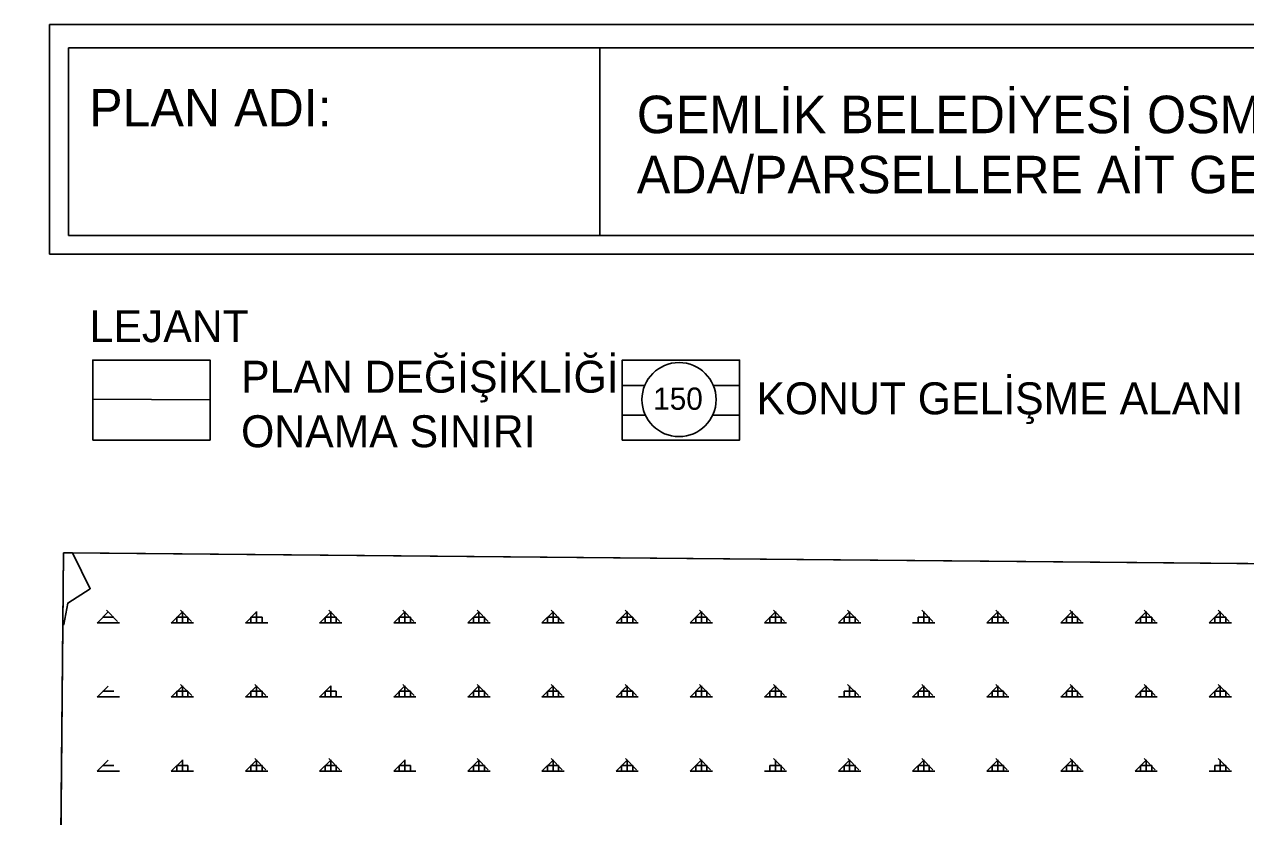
# Model space of a CAD drawing. Extents: x 427903 to 430077, y 4477233 to 4480385.
# Drawn here: x 427903 to 428726, y 4479851 to 4480385 of the extents above; entities that cross this region are included whole.
import ezdxf

# ---------------------------------------------------------------- set-up
doc = ezdxf.new("R2010")
doc.units = 0
for name, color, linetype in [('ADA', 7, 'Continuous'), ('Level 53', 7, 'Continuous'), ('PL_AYA_ORMAN', 7, 'Continuous'), ('PL_KA_TARIM_DIGER', 7, 'Continuous'), ('PL_KON_ONE_150', 7, 'Continuous'), ('rezerv yapı alan', 7, 'Continuous'), ('SM_DAIRE', 7, 'Continuous'), ('SM_TAKS', 7, 'Continuous'), ('SN_BMK Değişiklik', 7, 'Continuous'), ('SıNıR', 7, 'Continuous'), ('TR_ORMAN', 7, 'Continuous'), ('TR_ORTAGELISME', 7, 'Continuous')]:
    doc.layers.add(name, color=color, linetype=linetype)

msp = doc.modelspace()

# ---------------------------------------------------------------- linework, layer by layer
at = {"layer": 'ADA'}
for p, q in [((427935.26, 4480028.56), (427934.93, 4480028.9)), ((427946.96, 4480004.75), (427935.26, 4480028.56)), ((427931.77, 4479995.04), (427946.96, 4480004.75)), ((427929.05, 4479980.53), (427931.77, 4479995.04)), ((427928.55, 4479980.19), (427929.05, 4479980.53))]:
    msp.add_line(p, q, dxfattribs=at)
at = {"layer": 'Level 53'}
for p, q in [((427919.44, 4480385.36), (429266.95, 4480385.36)), ((427919.44, 4480230.37), (427919.44, 4480385.36)), ((427932.36, 4480369.55), (429254.03, 4480369.55)), ((427932.36, 4480243.03), (427932.36, 4480369.55)), ((428290.69, 4480369.55), (428290.69, 4480243.03)), ((427932.36, 4480243.03), (428290.69, 4480243.03)), ((428290.69, 4480243.03), (429254.03, 4480243.03)), ((427919.44, 4480230.37), (429266.95, 4480230.37))]:
    msp.add_line(p, q, dxfattribs=at)
for points in [[(427948.62, 4480105.05), (428027.85, 4480105.05), (428027.85, 4480158.93), (427948.62, 4480158.93), (427948.62, 4480105.05)], [(428305.75, 4480105.05), (428384.98, 4480105.05), (428384.98, 4480158.93), (428305.75, 4480158.93), (428305.75, 4480105.05)]]:
    msp.add_lwpolyline(points, dxfattribs=at)
at = {"layer": 'PL_AYA_ORMAN'}
for points in [[(427934.93, 4480028.9), (427935.26, 4480028.56), (427946.96, 4480004.75), (427931.77, 4479995.04), (427929.05, 4479980.53), (427928.55, 4479980.19)], [(429043.16, 4480018.9), (427934.93, 4480028.9)], [(427928.55, 4479980.19), (427923.1, 4479407.43)]]:
    msp.add_lwpolyline(points, dxfattribs=at)
at = {"layer": 'PL_KA_TARIM_DIGER'}
for points in [[(427928.55, 4479980.19), (427929.02, 4480028.95), (427934.93, 4480028.9)], [(427934.93, 4480028.9), (427935.26, 4480028.56), (427946.96, 4480004.75), (427931.77, 4479995.04), (427929.05, 4479980.53), (427928.55, 4479980.19)]]:
    msp.add_lwpolyline(points, dxfattribs=at)
at = {"layer": 'PL_KON_ONE_150'}
msp.add_lwpolyline([(428305.75, 4480158.93), (428305.75, 4480105.05), (428384.98, 4480105.05), (428384.98, 4480158.93), (428305.75, 4480158.93)], dxfattribs=at)
at = {"layer": 'rezerv yapı alan'}
msp.add_lwpolyline([(430040.04, 4478910.67), (430050.52, 4480009.82), (427929.02, 4480028.95), (427921.98, 4479290.57)], dxfattribs=at)
at = {"layer": 'SM_DAIRE'}
msp.add_circle((428344.11, 4480132.32), 25, dxfattribs=at)
at = {"layer": 'SN_BMK Değişiklik'}
msp.add_line((427948.62, 4480132.69), (428027.85, 4480132.13), dxfattribs=at)
at = {"layer": 'SıNıR'}
for p, q in [((427902.58, 4477253.75), (427929.02, 4480028.95)), ((427929.02, 4480028.95), (430050.52, 4480009.82))]:
    msp.add_line(p, q, dxfattribs=at)
at = {"layer": 'TR_ORMAN'}
for p, q in [((427951.63, 4479981.62), (427959.13, 4479989.12)), ((427965.36, 4479982.71), (427957.87, 4479990.21)), ((428001.63, 4479981.63), (428009.13, 4479989.13)), ((428015.36, 4479982.71), (428007.86, 4479990.21)), ((428009.14, 4479981.81), (428009.14, 4479989.31)), ((428051.63, 4479981.64), (428059.13, 4479989.13)), ((428059.14, 4479981.81), (428059.14, 4479989.31)), ((428101.63, 4479981.64), (428109.13, 4479989.14)), ((428115.34, 4479982.71), (428107.84, 4479990.21)), ((428109.14, 4479981.81), (428109.14, 4479989.31)), ((428109.14, 4479981.81), (428109.14, 4479989.31)), ((428151.63, 4479981.65), (428159.13, 4479989.15)), ((428165.33, 4479982.71), (428157.84, 4479990.21)), ((428159.14, 4479981.81), (428159.14, 4479989.31)), ((428159.14, 4479981.81), (428159.14, 4479989.31)), ((428201.63, 4479981.66), (428209.13, 4479989.16)), ((428215.33, 4479982.71), (428207.83, 4479990.21)), ((428209.14, 4479981.81), (428209.14, 4479989.31)), ((428251.63, 4479981.66), (428259.13, 4479989.16)), ((428265.32, 4479982.71), (428257.82, 4479990.21)), ((428259.14, 4479981.81), (428259.14, 4479989.31)), ((428301.63, 4479981.67), (428309.13, 4479989.17)), ((428315.31, 4479982.71), (428307.81, 4479990.21)), ((428309.14, 4479981.81), (428309.14, 4479989.31)), ((428351.63, 4479981.68), (428359.13, 4479989.18)), ((428365.3, 4479982.71), (428357.81, 4479990.21)), ((428359.14, 4479981.81), (428359.14, 4479989.31)), ((428401.63, 4479981.68), (428409.13, 4479989.18)), ((428415.3, 4479982.71), (428407.8, 4479990.21)), ((428409.14, 4479981.81), (428409.14, 4479989.31)), ((428409.14, 4479981.81), (428409.14, 4479989.31)), ((428451.63, 4479981.69), (428459.13, 4479989.19)), ((428465.29, 4479982.71), (428457.79, 4479990.21)), ((428459.14, 4479981.81), (428459.14, 4479989.31)), ((428515.28, 4479982.71), (428507.78, 4479990.21)), ((428509.14, 4479981.81), (428509.14, 4479989.31)), ((428551.63, 4479981.71), (428559.13, 4479989.2)), ((428565.27, 4479982.71), (428557.78, 4479990.21)), ((428559.14, 4479981.81), (428559.14, 4479989.31)), ((428601.63, 4479981.71), (428609.13, 4479989.21)), ((428615.27, 4479982.71), (428607.77, 4479990.21)), ((428609.14, 4479981.81), (428609.14, 4479989.31)), ((428651.63, 4479981.72), (428659.13, 4479989.22)), ((428665.26, 4479982.71), (428657.76, 4479990.21)), ((428659.14, 4479981.81), (428659.14, 4479989.31)), ((428701.63, 4479981.73), (428709.13, 4479989.23)), ((428715.25, 4479982.71), (428707.75, 4479990.21)), ((428709.14, 4479981.81), (428709.14, 4479989.31)), ((427951.64, 4479981.81), (427966.64, 4479981.81)), ((427955.39, 4479985.56), (427962.89, 4479985.56)), ((428001.64, 4479981.81), (428016.64, 4479981.81)), ((428005.39, 4479981.81), (428005.39, 4479985.56)), ((428005.39, 4479985.56), (428012.89, 4479985.56)), ((428012.89, 4479981.81), (428012.89, 4479985.56)), ((428051.64, 4479981.81), (428066.64, 4479981.81)), ((428055.39, 4479985.56), (428062.89, 4479985.56)), ((428055.39, 4479981.81), (428055.39, 4479985.56)), ((428062.89, 4479981.81), (428062.89, 4479985.56)), ((428101.64, 4479981.81), (428116.64, 4479981.81)), ((428105.39, 4479981.81), (428105.39, 4479985.56)), ((428105.39, 4479981.81), (428105.39, 4479985.56)), ((428105.39, 4479985.56), (428112.89, 4479985.56)), ((428112.89, 4479981.81), (428112.89, 4479985.56)), ((428151.64, 4479981.81), (428166.64, 4479981.81)), ((428155.39, 4479981.81), (428155.39, 4479985.56)), ((428155.39, 4479981.81), (428155.39, 4479985.56)), ((428155.39, 4479985.56), (428162.89, 4479985.56)), ((428162.89, 4479981.81), (428162.89, 4479985.56)), ((428162.89, 4479981.81), (428162.89, 4479985.56)), ((428201.64, 4479981.81), (428216.64, 4479981.81)), ((428205.39, 4479981.81), (428205.39, 4479985.56)), ((428205.39, 4479985.56), (428212.89, 4479985.56)), ((428212.89, 4479981.81), (428212.89, 4479985.56)), ((428251.64, 4479981.81), (428266.64, 4479981.81)), ((428255.39, 4479981.81), (428255.39, 4479985.56)), ((428255.39, 4479985.56), (428262.89, 4479985.56)), ((428262.89, 4479981.81), (428262.89, 4479985.56)), ((428301.64, 4479981.81), (428316.64, 4479981.81)), ((428305.39, 4479981.81), (428305.39, 4479985.56)), ((428305.39, 4479985.56), (428312.89, 4479985.56)), ((428312.89, 4479981.81), (428312.89, 4479985.56)), ((428351.64, 4479981.81), (428366.64, 4479981.81)), ((428355.39, 4479981.81), (428355.39, 4479985.56)), ((428355.39, 4479985.56), (428362.89, 4479985.56)), ((428362.89, 4479981.81), (428362.89, 4479985.56)), ((428362.89, 4479981.81), (428362.89, 4479985.56)), ((428401.64, 4479981.81), (428416.64, 4479981.81)), ((428405.39, 4479981.81), (428405.39, 4479985.56)), ((428405.39, 4479985.56), (428412.89, 4479985.56)), ((428412.89, 4479981.81), (428412.89, 4479985.56)), ((428412.89, 4479981.81), (428412.89, 4479985.56)), ((428451.64, 4479981.81), (428466.64, 4479981.81)), ((428455.39, 4479981.81), (428455.39, 4479985.56)), ((428455.39, 4479985.56), (428462.89, 4479985.56)), ((428462.89, 4479981.81), (428462.89, 4479985.56)), ((428501.64, 4479981.81), (428516.64, 4479981.81)), ((428505.39, 4479981.81), (428505.39, 4479985.56)), ((428505.39, 4479985.56), (428512.89, 4479985.56)), ((428512.89, 4479981.81), (428512.89, 4479985.56)), ((428551.64, 4479981.81), (428566.64, 4479981.81)), ((428555.39, 4479981.81), (428555.39, 4479985.56)), ((428555.39, 4479985.56), (428562.89, 4479985.56)), ((428562.89, 4479981.81), (428562.89, 4479985.56)), ((428601.64, 4479981.81), (428616.64, 4479981.81)), ((428605.39, 4479981.81), (428605.39, 4479985.56)), ((428605.39, 4479985.56), (428612.89, 4479985.56)), ((428612.89, 4479981.81), (428612.89, 4479985.56)), ((428651.64, 4479981.81), (428666.64, 4479981.81)), ((428655.39, 4479981.81), (428655.39, 4479985.56)), ((428655.39, 4479985.56), (428662.89, 4479985.56)), ((428662.89, 4479981.81), (428662.89, 4479985.56)), ((428701.64, 4479981.81), (428716.64, 4479981.81)), ((428705.39, 4479981.81), (428705.39, 4479985.56)), ((428705.39, 4479981.81), (428705.39, 4479985.56)), ((428705.39, 4479985.56), (428712.89, 4479985.56)), ((428712.89, 4479981.81), (428712.89, 4479985.56)), ((427951.63, 4479931.63), (427959.13, 4479939.13)), ((428001.63, 4479931.64), (428009.13, 4479939.13)), ((428015.39, 4479932.68), (428007.89, 4479940.18)), ((428009.14, 4479931.81), (428009.14, 4479939.31)), ((428051.63, 4479931.64), (428059.13, 4479939.14)), ((428065.38, 4479932.68), (428057.88, 4479940.18)), ((428059.14, 4479931.81), (428059.14, 4479939.31)), ((428101.63, 4479931.65), (428109.13, 4479939.15)), ((428109.14, 4479931.81), (428109.14, 4479939.31)), ((428109.14, 4479931.81), (428109.14, 4479939.31)), ((428151.63, 4479931.66), (428159.13, 4479939.16)), ((428165.37, 4479932.68), (428157.87, 4479940.18)), ((428159.14, 4479931.81), (428159.14, 4479939.31)), ((428159.14, 4479931.81), (428159.14, 4479939.31)), ((428201.63, 4479931.66), (428209.13, 4479939.16)), ((428215.36, 4479932.68), (428207.86, 4479940.18)), ((428209.14, 4479931.81), (428209.14, 4479939.31)), ((428251.63, 4479931.67), (428259.13, 4479939.17)), ((428265.35, 4479932.68), (428257.85, 4479940.18)), ((428259.14, 4479931.81), (428259.14, 4479939.31)), ((428301.63, 4479931.68), (428309.13, 4479939.18)), ((428315.34, 4479932.68), (428307.84, 4479940.18)), ((428309.14, 4479931.81), (428309.14, 4479939.31)), ((428351.63, 4479931.69), (428359.13, 4479939.18)), ((428365.34, 4479932.68), (428357.84, 4479940.18)), ((428359.14, 4479931.81), (428359.14, 4479939.31)), ((428401.63, 4479931.69), (428409.13, 4479939.19)), ((428415.33, 4479932.68), (428407.83, 4479940.18)), ((428409.14, 4479931.81), (428409.14, 4479939.31)), ((428409.14, 4479931.81), (428409.14, 4479939.31)), ((428465.32, 4479932.68), (428457.82, 4479940.18)), ((428459.14, 4479931.81), (428459.14, 4479939.31)), ((428501.63, 4479931.71), (428509.13, 4479939.21)), ((428515.31, 4479932.68), (428507.81, 4479940.18)), ((428509.14, 4479931.81), (428509.14, 4479939.31)), ((428551.63, 4479931.71), (428559.13, 4479939.21)), ((428565.31, 4479932.68), (428557.81, 4479940.18)), ((428559.14, 4479931.81), (428559.14, 4479939.31)), ((428601.63, 4479931.72), (428609.13, 4479939.22)), ((428615.3, 4479932.68), (428607.8, 4479940.18)), ((428609.14, 4479931.81), (428609.14, 4479939.31)), ((428651.63, 4479931.73), (428659.13, 4479939.23)), ((428665.29, 4479932.68), (428657.79, 4479940.18)), ((428659.14, 4479931.81), (428659.14, 4479939.31)), ((428701.63, 4479931.73), (428709.13, 4479939.23)), ((428715.28, 4479932.68), (428707.78, 4479940.18)), ((428709.14, 4479931.81), (428709.14, 4479939.31)), ((427951.64, 4479931.81), (427966.64, 4479931.81)), ((427955.39, 4479935.56), (427962.89, 4479935.56)), ((428001.64, 4479931.81), (428016.64, 4479931.81)), ((428005.39, 4479931.81), (428005.39, 4479935.56)), ((428005.39, 4479935.56), (428012.89, 4479935.56)), ((428012.89, 4479931.81), (428012.89, 4479935.56)), ((428051.64, 4479931.81), (428066.64, 4479931.81)), ((428055.39, 4479935.56), (428062.89, 4479935.56)), ((428055.39, 4479931.81), (428055.39, 4479935.56)), ((428062.89, 4479931.81), (428062.89, 4479935.56)), ((428101.64, 4479931.81), (428116.64, 4479931.81)), ((428105.39, 4479931.81), (428105.39, 4479935.56)), ((428105.39, 4479931.81), (428105.39, 4479935.56)), ((428105.39, 4479935.56), (428112.89, 4479935.56)), ((428112.89, 4479931.81), (428112.89, 4479935.56)), ((428151.64, 4479931.81), (428166.64, 4479931.81)), ((428155.39, 4479931.81), (428155.39, 4479935.56)), ((428155.39, 4479931.81), (428155.39, 4479935.56)), ((428155.39, 4479935.56), (428162.89, 4479935.56)), ((428162.89, 4479931.81), (428162.89, 4479935.56)), ((428162.89, 4479931.81), (428162.89, 4479935.56)), ((428201.64, 4479931.81), (428216.64, 4479931.81)), ((428205.39, 4479931.81), (428205.39, 4479935.56)), ((428205.39, 4479935.56), (428212.89, 4479935.56)), ((428212.89, 4479931.81), (428212.89, 4479935.56)), ((428251.64, 4479931.81), (428266.64, 4479931.81)), ((428255.39, 4479931.81), (428255.39, 4479935.56)), ((428255.39, 4479935.56), (428262.89, 4479935.56)), ((428262.89, 4479931.81), (428262.89, 4479935.56)), ((428301.64, 4479931.81), (428316.64, 4479931.81)), ((428305.39, 4479931.81), (428305.39, 4479935.56)), ((428305.39, 4479935.56), (428312.89, 4479935.56)), ((428312.89, 4479931.81), (428312.89, 4479935.56)), ((428351.64, 4479931.81), (428366.64, 4479931.81)), ((428355.39, 4479931.81), (428355.39, 4479935.56)), ((428355.39, 4479935.56), (428362.89, 4479935.56)), ((428362.89, 4479931.81), (428362.89, 4479935.56)), ((428362.89, 4479931.81), (428362.89, 4479935.56)), ((428401.64, 4479931.81), (428416.64, 4479931.81)), ((428405.39, 4479931.81), (428405.39, 4479935.56)), ((428405.39, 4479935.56), (428412.89, 4479935.56)), ((428412.89, 4479931.81), (428412.89, 4479935.56)), ((428412.89, 4479931.81), (428412.89, 4479935.56)), ((428451.64, 4479931.81), (428466.64, 4479931.81)), ((428455.39, 4479931.81), (428455.39, 4479935.56)), ((428455.39, 4479935.56), (428462.89, 4479935.56)), ((428462.89, 4479931.81), (428462.89, 4479935.56)), ((428501.64, 4479931.81), (428516.64, 4479931.81)), ((428505.39, 4479931.81), (428505.39, 4479935.56)), ((428505.39, 4479935.56), (428512.89, 4479935.56)), ((428512.89, 4479931.81), (428512.89, 4479935.56)), ((428551.64, 4479931.81), (428566.64, 4479931.81)), ((428555.39, 4479931.81), (428555.39, 4479935.56)), ((428555.39, 4479935.56), (428562.89, 4479935.56)), ((428562.89, 4479931.81), (428562.89, 4479935.56)), ((428601.64, 4479931.81), (428616.64, 4479931.81)), ((428605.39, 4479931.81), (428605.39, 4479935.56)), ((428605.39, 4479935.56), (428612.89, 4479935.56)), ((428612.89, 4479931.81), (428612.89, 4479935.56)), ((428651.64, 4479931.81), (428666.64, 4479931.81)), ((428655.39, 4479931.81), (428655.39, 4479935.56)), ((428655.39, 4479935.56), (428662.89, 4479935.56)), ((428662.89, 4479931.81), (428662.89, 4479935.56)), ((428701.64, 4479931.81), (428716.64, 4479931.81)), ((428705.39, 4479931.81), (428705.39, 4479935.56)), ((428705.39, 4479931.81), (428705.39, 4479935.56)), ((428705.39, 4479935.56), (428712.89, 4479935.56)), ((428712.89, 4479931.81), (428712.89, 4479935.56)), ((427951.63, 4479881.64), (427959.13, 4479889.14)), ((428001.63, 4479881.64), (428009.13, 4479889.14)), ((428009.14, 4479881.81), (428009.14, 4479889.31)), ((428051.63, 4479881.65), (428059.13, 4479889.15)), ((428065.41, 4479882.66), (428057.91, 4479890.16)), ((428059.14, 4479881.81), (428059.14, 4479889.31)), ((428101.63, 4479881.66), (428109.13, 4479889.16)), ((428115.41, 4479882.66), (428107.91, 4479890.16)), ((428109.14, 4479881.81), (428109.14, 4479889.31)), ((428109.14, 4479881.81), (428109.14, 4479889.31)), ((428151.63, 4479881.66), (428159.13, 4479889.16)), ((428159.14, 4479881.81), (428159.14, 4479889.31)), ((428159.14, 4479881.81), (428159.14, 4479889.31)), ((428201.63, 4479881.67), (428209.13, 4479889.17)), ((428215.39, 4479882.66), (428207.89, 4479890.16)), ((428209.14, 4479881.81), (428209.14, 4479889.31)), ((428251.63, 4479881.68), (428259.13, 4479889.18)), ((428265.38, 4479882.66), (428257.88, 4479890.16)), ((428259.14, 4479881.81), (428259.14, 4479889.31)), ((428301.63, 4479881.69), (428309.13, 4479889.18)), ((428315.38, 4479882.66), (428307.88, 4479890.16)), ((428309.14, 4479881.81), (428309.14, 4479889.31)), ((428351.63, 4479881.69), (428359.13, 4479889.19)), ((428365.37, 4479882.66), (428357.87, 4479890.16)), ((428359.14, 4479881.81), (428359.14, 4479889.31)), ((428415.36, 4479882.66), (428407.86, 4479890.16)), ((428409.14, 4479881.81), (428409.14, 4479889.31)), ((428409.14, 4479881.81), (428409.14, 4479889.31)), ((428451.63, 4479881.71), (428459.13, 4479889.21)), ((428465.35, 4479882.66), (428457.85, 4479890.16)), ((428459.14, 4479881.81), (428459.14, 4479889.31)), ((428501.63, 4479881.71), (428509.13, 4479889.21)), ((428515.35, 4479882.66), (428507.85, 4479890.16)), ((428509.14, 4479881.81), (428509.14, 4479889.31)), ((428551.63, 4479881.72), (428559.13, 4479889.22)), ((428565.34, 4479882.66), (428557.84, 4479890.16)), ((428559.14, 4479881.81), (428559.14, 4479889.31)), ((428601.63, 4479881.73), (428609.13, 4479889.23)), ((428615.33, 4479882.66), (428607.83, 4479890.16)), ((428609.14, 4479881.81), (428609.14, 4479889.31)), ((428651.63, 4479881.74), (428659.13, 4479889.23)), ((428665.32, 4479882.66), (428657.82, 4479890.16)), ((428659.14, 4479881.81), (428659.14, 4479889.31)), ((428715.31, 4479882.66), (428707.82, 4479890.16)), ((428709.14, 4479881.81), (428709.14, 4479889.31)), ((427951.64, 4479881.81), (427966.64, 4479881.81)), ((427955.39, 4479885.56), (427962.89, 4479885.56)), ((428001.64, 4479881.81), (428016.64, 4479881.81)), ((428005.39, 4479881.81), (428005.39, 4479885.56)), ((428005.39, 4479885.56), (428012.89, 4479885.56)), ((428012.89, 4479881.81), (428012.89, 4479885.56)), ((428051.64, 4479881.81), (428066.64, 4479881.81)), ((428055.39, 4479885.56), (428062.89, 4479885.56)), ((428055.39, 4479881.81), (428055.39, 4479885.56)), ((428062.89, 4479881.81), (428062.89, 4479885.56)), ((428101.64, 4479881.81), (428116.64, 4479881.81)), ((428105.39, 4479881.81), (428105.39, 4479885.56)), ((428105.39, 4479881.81), (428105.39, 4479885.56)), ((428105.39, 4479885.56), (428112.89, 4479885.56)), ((428112.89, 4479881.81), (428112.89, 4479885.56)), ((428151.64, 4479881.81), (428166.64, 4479881.81)), ((428155.39, 4479881.81), (428155.39, 4479885.56)), ((428155.39, 4479881.81), (428155.39, 4479885.56)), ((428155.39, 4479885.56), (428162.89, 4479885.56)), ((428162.89, 4479881.81), (428162.89, 4479885.56)), ((428162.89, 4479881.81), (428162.89, 4479885.56)), ((428201.64, 4479881.81), (428216.64, 4479881.81)), ((428205.39, 4479881.81), (428205.39, 4479885.56)), ((428205.39, 4479885.56), (428212.89, 4479885.56)), ((428212.89, 4479881.81), (428212.89, 4479885.56)), ((428251.64, 4479881.81), (428266.64, 4479881.81)), ((428255.39, 4479881.81), (428255.39, 4479885.56)), ((428255.39, 4479885.56), (428262.89, 4479885.56)), ((428262.89, 4479881.81), (428262.89, 4479885.56)), ((428301.64, 4479881.81), (428316.64, 4479881.81)), ((428305.39, 4479881.81), (428305.39, 4479885.56)), ((428305.39, 4479885.56), (428312.89, 4479885.56)), ((428312.89, 4479881.81), (428312.89, 4479885.56)), ((428351.64, 4479881.81), (428366.64, 4479881.81)), ((428355.39, 4479881.81), (428355.39, 4479885.56)), ((428355.39, 4479885.56), (428362.89, 4479885.56)), ((428362.89, 4479881.81), (428362.89, 4479885.56)), ((428362.89, 4479881.81), (428362.89, 4479885.56)), ((428401.64, 4479881.81), (428416.64, 4479881.81)), ((428405.39, 4479881.81), (428405.39, 4479885.56)), ((428405.39, 4479885.56), (428412.89, 4479885.56)), ((428412.89, 4479881.81), (428412.89, 4479885.56)), ((428412.89, 4479881.81), (428412.89, 4479885.56)), ((428451.64, 4479881.81), (428466.64, 4479881.81)), ((428455.39, 4479881.81), (428455.39, 4479885.56)), ((428455.39, 4479885.56), (428462.89, 4479885.56)), ((428462.89, 4479881.81), (428462.89, 4479885.56)), ((428501.64, 4479881.81), (428516.64, 4479881.81)), ((428505.39, 4479881.81), (428505.39, 4479885.56)), ((428505.39, 4479885.56), (428512.89, 4479885.56)), ((428512.89, 4479881.81), (428512.89, 4479885.56)), ((428551.64, 4479881.81), (428566.64, 4479881.81)), ((428555.39, 4479881.81), (428555.39, 4479885.56)), ((428555.39, 4479885.56), (428562.89, 4479885.56)), ((428562.89, 4479881.81), (428562.89, 4479885.56)), ((428601.64, 4479881.81), (428616.64, 4479881.81)), ((428605.39, 4479881.81), (428605.39, 4479885.56)), ((428605.39, 4479885.56), (428612.89, 4479885.56)), ((428612.89, 4479881.81), (428612.89, 4479885.56)), ((428651.64, 4479881.81), (428666.64, 4479881.81)), ((428655.39, 4479881.81), (428655.39, 4479885.56)), ((428655.39, 4479885.56), (428662.89, 4479885.56)), ((428662.89, 4479881.81), (428662.89, 4479885.56)), ((428701.64, 4479881.81), (428716.64, 4479881.81)), ((428705.39, 4479881.81), (428705.39, 4479885.56)), ((428705.39, 4479881.81), (428705.39, 4479885.56)), ((428705.39, 4479885.56), (428712.89, 4479885.56)), ((428712.89, 4479881.81), (428712.89, 4479885.56))]:
    msp.add_line(p, q, dxfattribs=at)
at = {"layer": 'TR_ORTAGELISME'}
for p, q in [((428305.75, 4480141.92), (428321.03, 4480141.92)), ((428367.19, 4480141.92), (428384.98, 4480141.92)), ((428305.75, 4480121.92), (428321.37, 4480121.92)), ((428366.84, 4480121.92), (428384.98, 4480121.92))]:
    msp.add_line(p, q, dxfattribs=at)
msp.add_lwpolyline([(428305.75, 4480158.93), (428305.75, 4480105.05), (428384.98, 4480105.05), (428384.98, 4480158.93), (428305.75, 4480158.93)], dxfattribs=at)

# ---------------------------------------------------------------- texts
at = {"layer": 'Level 53'}
for s, height, p in [('PLAN ADI:', 25.305, (427946.21, 4480316.6)), ('GEMLİK BELEDİYESİ OSMANİYE MAHALLESİ, H22A09A PAFTA, 1064/1 VE 1076/5 ', 25.3046, (428315.64, 4480311.99)), ('ADA/PARSELLERE AİT GEMLİK 1/5000 ÖLÇEKLİ NAZIM İMAR PLANI DEĞİŞİKLİĞİ', 25.3046, (428315.64, 4480271.46)), ('LEJANT', 21.553, (427946.57, 4480171.08)), ('PLAN DEĞİŞİKLİĞİ', 21.553, (428048.7, 4480136.98)), ('KONUT GELİŞME ALANI', 21.553, (428396.24, 4480122.39)), ('ONAMA SINIRI', 21.553, (428048.7, 4480100.2))]:
    msp.add_text(s, height=height, rotation=360, dxfattribs=at).set_placement(p)
at = {"layer": 'SM_TAKS'}
msp.add_text('150', height=15, dxfattribs=at).set_placement((428326.66, 4480125.45))

doc.saveas('drawing.dxf')
